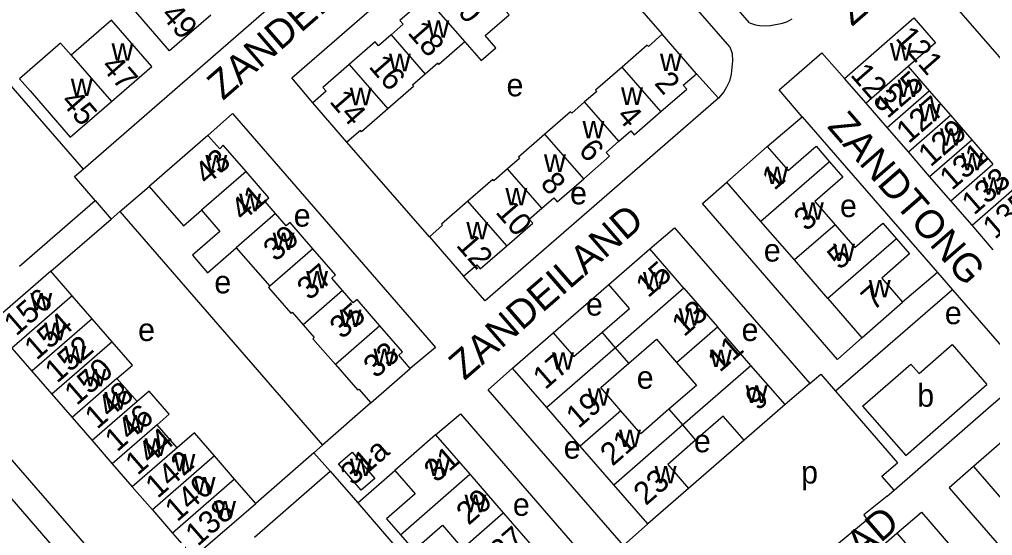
# Model space of a CAD drawing. Extents: x 155854 to 157362, y 383621 to 384685.
# Drawn here: x 156327 to 156498.5, y 384265.7 to 384356.7 of the extents above; entities that cross this region are included whole.
import ezdxf

# ---------------------------------------------------------------- set-up
doc = ezdxf.new("R2010")
doc.units = 0
for name, color, linetype in [('BLT_Basislijn', 7, 'Continuous'), ('BLT_Bebouwing', 7, 'Continuous'), ('BLT_Centroide', 7, 'Continuous'), ('BLT_Huisnummer', 7, 'Continuous'), ('BLT_Huisnummer_ tussenligend', 7, 'Continuous'), ('BLT_Huisnummer_reeks', 7, 'Continuous'), ('BLT_Onderverdeling_panden', 7, 'Continuous'), ('BLT_Straatnaam', 7, 'Continuous')]:
    doc.layers.add(name, color=color, linetype=linetype)

msp = doc.modelspace()

# ---------------------------------------------------------------- linework, layer by layer
at = {"layer": 'BLT_Basislijn'}
for p, q in [((156455.68, 384356.1), (156428.51, 384387.53)), ((156374.97, 384346.36), (156416.08, 384382.07)), ((156452.19, 384351.84), (156425.12, 384382.99)), ((156425.8, 384370.74), (156440.3, 384354.06)), ((156489.82, 384361.43), (156521.66, 384324.72)), ((156317.2, 384354.46), (156338.19, 384330.3)), ((156378.7, 384342), (156374.97, 384346.36)), ((156446.34, 384347.11), (156450.18, 384342.81)), ((156450.18, 384342.81), (156409.08, 384307.1)), ((156360.19, 384336.24), (156364.52, 384340.09)), ((156364.52, 384340.09), (156400.31, 384298.89)), ((156458.81, 384334.27), (156464.96, 384339.52)), ((156464.96, 384339.52), (156488.82, 384312.06)), ((156399.24, 384318.36), (156384.72, 384335.05)), ((156344.7, 384322.81), (156349.83, 384327.25)), ((156447.36, 384324.22), (156451.65, 384328.02)), ((156340.32, 384324.8), (156343.15, 384321.47)), ((156471.21, 384296.77), (156447.36, 384324.22)), ((156332.5, 384312.33), (156343.15, 384321.47)), ((156343.15, 384321.47), (156344.7, 384322.81)), ((156344.7, 384322.81), (156380.43, 384281.68)), ((156438.08, 384316.24), (156442.45, 384319.96)), ((156442.45, 384319.96), (156466.3, 384292.51)), ((156409.08, 384307.1), (156405.27, 384311.42)), ((156488.82, 384312.06), (156482.64, 384306.84)), ((156488.82, 384312.06), (156491.44, 384309.04)), ((156421.07, 384301.47), (156430.86, 384309.97)), ((156491.44, 384309.04), (156470.84, 384291.15)), ((156491.44, 384309.04), (156502.92, 384295.83)), ((156344.96, 384249.98), (156295.38, 384307.06)), ((156475.48, 384300.58), (156471.21, 384296.77)), ((156400.31, 384298.89), (156395.87, 384295.16)), ((156409.61, 384291.43), (156413.91, 384295.21)), ((156466.3, 384292.51), (156468.22, 384294.17)), ((156468.22, 384294.17), (156470.84, 384291.15)), ((156497.78, 384288.23), (156504.47, 384294.05)), ((156466.3, 384292.51), (156461.94, 384288.8)), ((156433.47, 384263.98), (156409.61, 384291.43)), ((156470.84, 384291.15), (156481.75, 384278.57)), ((156388.92, 384289.13), (156380.43, 384281.68)), ((156400.34, 384283.46), (156404.71, 384287.17)), ((156404.71, 384287.17), (156428.56, 384259.71)), ((156481.15, 384273.74), (156497.78, 384288.23)), ((156454.73, 384282.52), (156444.91, 384274.03)), ((156378.87, 384280.31), (156368.63, 384271.4)), ((156380.43, 384281.68), (156378.87, 384280.31)), ((156381.78, 384277.07), (156378.87, 384280.31)), ((156368.42, 384265.44), (156381.78, 384277.07)), ((156381.78, 384277.07), (156386.64, 384271.48)), ((156386.64, 384271.48), (156393.16, 384277.21)), ((156495.16, 384277.93), (156490.89, 384274.12)), ((156479.96, 384272.7), (156481.15, 384273.74)), ((156490.89, 384274.12), (156524.57, 384235.35)), ((156386.64, 384271.48), (156410.41, 384244.02)), ((156481.63, 384266.16), (156485.98, 384269.86)), ((156485.98, 384269.86), (156519.66, 384231.09)), ((156437.74, 384267.78), (156433.47, 384263.98))]:
    msp.add_line(p, q, dxfattribs=at)
for points in [[(156338.19, 384330.3), (156408.21, 384391.13)], [(156455.68, 384356.1), (156456.7, 384355.72), (156457.42, 384355.63), (156458.43, 384355.53), (156459.35, 384355.59), (156461.51, 384356.02), (156462.36, 384356.31), (156463.21, 384356.78)], [(156452.19, 384351.84), (156452.62, 384350.65), (156452.65, 384349.41), (156452.42, 384347.05), (156452.16, 384345.78), (156451.6, 384344.76), (156451.14, 384343.95), (156450.18, 384342.81)], [(156464.96, 384339.52), (156460.88, 384344.27), (156468.44, 384350.79), (156472.41, 384346.29)], [(156270.87, 384342.04), (156329.13, 384275), (156387.17, 384208.19)], [(156340.32, 384324.8), (156336.68, 384328.99), (156338.19, 384330.3)], [(156326.98, 384313.22), (156340.32, 384324.8)], [(156481.15, 384273.74), (156479.02, 384276.18), (156481.75, 384278.57)], [(156479.96, 384272.7), (156475.8, 384269.36), (156476.43, 384268.53), (156471.37, 384264.31), (156463.99, 384258.81), (156457.44, 384254.28), (156446.67, 384247.59)]]:
    msp.add_lwpolyline(points, dxfattribs=at)
at = {"layer": 'BLT_Bebouwing'}
for p, q in [((156343.23, 384356.56), (156336.12, 384350.38)), ((156446.34, 384347.11), (156440.3, 384354.06)), ((156476.21, 384341.92), (156472.41, 384346.29)), ((156384.72, 384335.05), (156378.7, 384342)), ((156479.93, 384337.64), (156476.21, 384341.92)), ((156483.67, 384333.33), (156479.93, 384337.64)), ((156360.19, 384336.24), (156349.83, 384327.25)), ((156451.65, 384328.02), (156458.81, 384334.27)), ((156487.41, 384329.02), (156483.67, 384333.33)), ((156491.16, 384324.72), (156487.41, 384329.02)), ((156457.68, 384321.08), (156451.65, 384328.02)), ((156494.9, 384320.41), (156491.16, 384324.72)), ((156463.58, 384314.29), (156457.68, 384321.08)), ((156498.65, 384316.1), (156494.9, 384320.41)), ((156399.24, 384318.36), (156405.27, 384311.42)), ((156365.19, 384316.44), (156371.1, 384309.65)), ((156444.11, 384309.31), (156438.08, 384316.24)), ((156469.48, 384307.49), (156463.58, 384314.29)), ((156332.5, 384312.33), (156322.37, 384303.51)), ((156339.8, 384303.93), (156336.26, 384308)), ((156444.11, 384309.31), (156450.02, 384302.51)), ((156469.48, 384307.49), (156475.48, 384300.58)), ((156475.48, 384300.58), (156482.64, 384306.84)), ((156343.34, 384299.86), (156339.8, 384303.93)), ((156421.1, 384301.42), (156421.11, 384301.42)), ((156455.92, 384295.72), (156450.02, 384302.51)), ((156461.94, 384288.8), (156455.92, 384295.72)), ((156388.92, 384289.13), (156395.87, 384295.16)), ((156419.92, 384288.29), (156413.91, 384295.21)), ((156347.71, 384289.34), (156344.16, 384293.42)), ((156425.83, 384281.49), (156419.92, 384288.29)), ((156354.79, 384281.19), (156351.25, 384285.26)), ((156502.37, 384284.18), (156495.16, 384277.93)), ((156400.34, 384283.46), (156393.16, 384277.21)), ((156400.34, 384283.46), (156406.37, 384276.53)), ((156431.73, 384274.7), (156425.83, 384281.49)), ((156364.92, 384275.68), (156361.39, 384279.77)), ((156495.16, 384277.93), (156500.88, 384271.35)), ((156368.63, 384271.4), (156364.92, 384275.68)), ((156406.37, 384276.53), (156412.27, 384269.73)), ((156437.74, 384267.78), (156431.73, 384274.7)), ((156412.27, 384269.73), (156418.18, 384262.93)), ((156474.43, 384259.91), (156481.63, 384266.16)), ((156481.63, 384266.16), (156487.34, 384259.59))]:
    msp.add_line(p, q, dxfattribs=at)
for points in [[(156360.7, 384357.43), (156353.45, 384351.15), (156346.37, 384359.3)], [(156398.69, 384360.55), (156394.03, 384356.5), (156394.62, 384355.83), (156392.48, 384353.98)], [(156405.5, 384352.71), (156408.35, 384349.42), (156410.96, 384351.68), (156409.09, 384353.84), (156413.28, 384357.48), (156412.1, 384358.83)], [(156343.2, 384342.23), (156350.31, 384348.4), (156343.23, 384356.56)], [(156472.41, 384346.29), (156484.66, 384356.95)], [(156484.66, 384356.95), (156488.45, 384352.58), (156483.62, 384348.38)], [(156440.3, 384354.06), (156437.85, 384351.92), (156437.65, 384352.15), (156433.21, 384348.28)], [(156336.12, 384350.38), (156334.21, 384352.5), (156327, 384346.24), (156328.87, 384344.09), (156335.95, 384335.94), (156343.2, 384342.23)], [(156392.48, 384353.98), (156390.27, 384352.05), (156389.68, 384352.72), (156385.11, 384348.75)], [(156405.5, 384352.71), (156400.92, 384348.72), (156400.72, 384348.95), (156398.51, 384347.03)], [(156385.11, 384348.75), (156380.44, 384344.7), (156381.03, 384344.03), (156378.7, 384342)], [(156433.21, 384348.28), (156428.54, 384344.23), (156428.74, 384344), (156426.61, 384342.15)], [(156483.62, 384348.38), (156487.35, 384344.09)], [(156398.51, 384347.03), (156396.27, 384345.09), (156396.47, 384344.86), (156391.92, 384340.91)], [(156440.03, 384340.43), (156444.6, 384344.4), (156443.99, 384345.07), (156446.34, 384347.11)], [(156487.35, 384344.09), (156491.09, 384339.78)], [(156426.61, 384342.15), (156424.33, 384340.17), (156424.13, 384340.39), (156419.62, 384336.48)], [(156391.92, 384340.91), (156387.3, 384336.9), (156387.11, 384337.12), (156384.72, 384335.05)], [(156432.64, 384335.21), (156434.77, 384337.05), (156435.36, 384336.37), (156440.03, 384340.43)], [(156491.09, 384339.78), (156494.84, 384335.47)], [(156366.92, 384329.87), (156362.9, 384334.51), (156362.31, 384333.89), (156360.19, 384336.24)], [(156419.62, 384336.48), (156414.93, 384332.4), (156415.13, 384332.18), (156413.03, 384330.35)], [(156426.45, 384328.62), (156431, 384332.59), (156430.41, 384333.26), (156432.64, 384335.21)], [(156494.84, 384335.47), (156498.58, 384331.17)], [(156458.81, 384334.27), (156462.48, 384330.04), (156467.41, 384334.33), (156469.79, 384331.59)], [(156413.03, 384330.35), (156410.62, 384328.26), (156410.43, 384328.49), (156406.04, 384324.67)], [(156469.79, 384331.59), (156472.13, 384328.89), (156467.2, 384324.61), (156470.75, 384320.51)], [(156372.14, 384322.48), (156370.24, 384324.67), (156370.92, 384325.26), (156366.92, 384329.87)], [(156419.06, 384323.4), (156421.17, 384325.24), (156421.77, 384324.55), (156426.45, 384328.62)], [(156349.83, 384327.25), (156355.88, 384320.29), (156359.07, 384323.05)], [(156406.04, 384324.67), (156401.38, 384320.62), (156401.58, 384320.4), (156399.24, 384318.36)], [(156412.88, 384316.8), (156417.45, 384320.76), (156416.82, 384321.46), (156419.06, 384323.4)], [(156359.07, 384323.05), (156362.3, 384319.32), (156357.46, 384315.12), (156360.14, 384312.04), (156365.2, 384316.44)], [(156378.72, 384316.28), (156374.69, 384320.91), (156374.02, 384320.32), (156372.14, 384322.48)], [(156470.75, 384320.51), (156474.25, 384316.5), (156479.18, 384320.78), (156481.59, 384318.01)], [(156405.27, 384311.42), (156407.6, 384313.44), (156408.2, 384312.75), (156412.88, 384316.8)], [(156481.59, 384318.01), (156483.9, 384315.35), (156478.97, 384311.06), (156482.64, 384306.84)], [(156383.94, 384308.89), (156382.03, 384311.09), (156382.72, 384311.68), (156378.72, 384316.28)], [(156430.86, 384309.97), (156438.08, 384316.24)], [(156336.26, 384308), (156332.5, 384312.33)], [(156371.1, 384309.65), (156370.87, 384309.45), (156374.81, 384304.92), (156375.03, 384305.12), (156377, 384302.86)], [(156429.68, 384301.55), (156434.52, 384305.76), (156430.86, 384309.97)], [(156390.53, 384302.69), (156386.5, 384307.33), (156385.82, 384306.73), (156383.94, 384308.89)], [(156377, 384302.86), (156378.94, 384300.62), (156378.72, 384300.42), (156382.67, 384295.87)], [(156395.87, 384295.16), (156393.84, 384297.5), (156394.53, 384298.09), (156390.53, 384302.69)], [(156413.91, 384295.21), (156421.07, 384301.47)], [(156421.07, 384301.47), (156424.73, 384297.26), (156429.68, 384301.55)], [(156344.16, 384293.42), (156346.89, 384295.78), (156343.34, 384299.86)], [(156434.4, 384296.12), (156439.25, 384300.33), (156442.8, 384296.24)], [(156475.61, 384288.51), (156484.13, 384295.93), (156485.55, 384294.3), (156491.39, 384299.39), (156497.52, 384292.33)], [(156325.63, 384298.77), (156329.17, 384294.7)], [(156382.67, 384295.87), (156386.61, 384291.34), (156386.83, 384291.53), (156388.92, 384289.13)], [(156433.01, 384287.73), (156429.45, 384291.82), (156434.4, 384296.12)], [(156442.8, 384296.24), (156446.32, 384292.19), (156441.47, 384287.98)], [(156329.17, 384294.7), (156332.71, 384290.62)], [(156495.65, 384290.69), (156497.52, 384292.33)], [(156332.71, 384290.62), (156336.25, 384286.54)], [(156351.25, 384285.26), (156353.38, 384287.12), (156349.83, 384291.2), (156347.71, 384289.34)], [(156483.2, 384279.84), (156495.65, 384290.69)], [(156441.47, 384287.98), (156436.52, 384283.68), (156433.01, 384287.73)], [(156461.94, 384288.8), (156454.73, 384282.52)], [(156475.61, 384288.51), (156483.2, 384279.84)], [(156336.25, 384286.54), (156339.79, 384282.47)], [(156454.73, 384282.52), (156451.05, 384286.76), (156446.17, 384282.52)], [(156361.39, 384279.77), (156357.85, 384283.85), (156354.79, 384281.19)], [(156339.79, 384282.47), (156343.34, 384278.39)], [(156446.17, 384282.52), (156441.25, 384278.25), (156444.91, 384274.03)], [(156385.25, 384280.08), (156385.65, 384280.43)], [(156385.65, 384280.43), (156389.61, 384275.8)], [(156383.25, 384278.39), (156385.25, 384280.08)], [(156343.34, 384278.39), (156346.88, 384274.31)], [(156387.2, 384273.75), (156383.25, 384278.39)], [(156393.16, 384277.21), (156396.74, 384273.09), (156391.68, 384268.7), (156394.14, 384265.87)], [(156389.61, 384275.8), (156387.2, 384273.75)], [(156346.88, 384274.31), (156350.42, 384270.24)], [(156444.91, 384274.03), (156437.74, 384267.78)], [(156350.42, 384270.24), (156353.96, 384266.16)], [(156353.96, 384266.16), (156357.66, 384261.91), (156368.63, 384271.4)], [(156394.14, 384265.87), (156396.49, 384263.17), (156401.55, 384267.55), (156405.09, 384263.47)]]:
    msp.add_lwpolyline(points, dxfattribs=at)
at = {"layer": 'BLT_Onderverdeling_panden'}
for p, q in [((156398.69, 384360.55), (156405.5, 384352.71)), ((156392.48, 384353.98), (156398.51, 384347.03)), ((156336.12, 384350.38), (156343.2, 384342.23)), ((156385.11, 384348.75), (156391.92, 384340.91)), ((156440.03, 384340.43), (156433.21, 384348.28)), ((156483.62, 384348.38), (156476.21, 384341.92)), ((156479.93, 384337.64), (156487.35, 384344.09)), ((156432.64, 384335.21), (156426.61, 384342.15)), ((156483.67, 384333.33), (156491.09, 384339.78)), ((156426.45, 384328.62), (156419.62, 384336.48)), ((156487.41, 384329.02), (156494.84, 384335.47)), ((156419.06, 384323.4), (156413.03, 384330.35)), ((156469.79, 384331.59), (156457.68, 384321.08)), ((156491.16, 384324.72), (156498.58, 384331.17)), ((156366.92, 384329.87), (156359.07, 384323.05)), ((156494.9, 384320.41), (156502.33, 384326.86)), ((156412.88, 384316.8), (156406.04, 384324.67)), ((156372.14, 384322.48), (156365.19, 384316.44)), ((156470.75, 384320.51), (156463.58, 384314.29)), ((156481.59, 384318.01), (156469.48, 384307.49)), ((156378.72, 384316.28), (156371.1, 384309.65)), ((156336.26, 384308), (156325.63, 384298.77)), ((156383.94, 384308.89), (156377, 384302.86)), ((156444.11, 384309.31), (156432.05, 384298.83)), ((156339.8, 384303.93), (156329.17, 384294.7)), ((156390.53, 384302.69), (156382.67, 384295.87)), ((156432.05, 384298.83), (156429.68, 384301.55)), ((156442.8, 384296.24), (156450.02, 384302.51)), ((156343.34, 384299.86), (156332.71, 384290.62)), ((156432.05, 384298.83), (156419.92, 384288.29)), ((156434.4, 384296.12), (156432.05, 384298.83)), ((156443.86, 384285.24), (156455.92, 384295.72)), ((156344.16, 384293.42), (156336.25, 384286.54)), ((156347.71, 384289.34), (156339.79, 384282.47)), ((156433.01, 384287.73), (156425.83, 384281.49)), ((156441.47, 384287.98), (156443.86, 384285.24)), ((156351.25, 384285.26), (156343.34, 384278.39)), ((156431.73, 384274.7), (156443.86, 384285.24)), ((156443.86, 384285.24), (156446.17, 384282.52)), ((156354.79, 384281.19), (156346.88, 384274.31)), ((156361.39, 384279.77), (156350.42, 384270.24)), ((156364.92, 384275.68), (156353.96, 384266.16)), ((156394.14, 384265.87), (156406.37, 384276.53)), ((156405.09, 384263.47), (156412.27, 384269.73))]:
    msp.add_line(p, q, dxfattribs=at)

# ---------------------------------------------------------------- texts
at = {"layer": 'BLT_Centroide'}
for s, p in [('w', (156398.89, 384353.45)), ('w', (156343.22, 384349.39)), ('w', (156480.42, 384349.44)), ('w', (156392.11, 384347.56)), ('w', (156439.88, 384347.59)), ('w', (156336.03, 384343.16)), ('e', (156412.84, 384343.13)), ('w', (156481.78, 384343)), ('w', (156385.21, 384341.56)), ('w', (156433.03, 384341.62)), ('w', (156485.51, 384338.72)), ('w', (156426.23, 384335.72)), ('w', (156489.26, 384334.41)), ('w', (156359.75, 384329.73)), ('w', (156419.44, 384329.81)), ('w', (156492.99, 384330.09)), ('w', (156458.62, 384327.69)), ('w', (156496.74, 384325.78)), ('w', (156412.64, 384323.92)), ('e', (156424.04, 384324.09)), ('w', (156365.72, 384322.88)), ('e', (156471.62, 384321.85)), ('e', (156375.33, 384320.17)), ('w', (156464.91, 384321.39)), ('w', (156405.75, 384317.94)), ('w', (156371.62, 384316.06)), ('e', (156458.19, 384314.01)), ('w', (156470.41, 384314.12)), ('e', (156361.34, 384308.41)), ('w', (156377.52, 384309.28)), ('w', (156436.89, 384309.12)), ('w', (156476.69, 384307.69)), ('w', (156328.9, 384305.41)), ('e', (156426.84, 384304.49)), ('e', (156490.1, 384302.98)), ('w', (156383.42, 384302.47)), ('w', (156443.18, 384302.72)), ('w', (156331.35, 384300.16)), ('e', (156347.9, 384300.01)), ('e', (156454.27, 384300.01)), ('w', (156334.9, 384296.09)), ('w', (156389.38, 384295.62)), ('w', (156420.86, 384294.94)), ('w', (156448.7, 384295.41)), ('w', (156338.43, 384292.03)), ('e', (156435.79, 384291.61)), ('b', (156485.24, 384288.44)), ('w', (156341.98, 384287.94)), ('w', (156427.16, 384288.62)), ('w', (156454.99, 384289.12)), ('w', (156345.52, 384283.88)), ('w', (156432.67, 384281.34)), ('w', (156349.05, 384279.78)), ('e', (156422.92, 384279.29)), ('e', (156445.87, 384280.41)), ('w', (156354.13, 384277.03)), ('w', (156385.23, 384276.22)), ('w', (156399.03, 384276.22)), ('w', (156438.95, 384274.91)), ('p', (156464.77, 384274.9)), ('w', (156357.68, 384272.97)), ('w', (156361.3, 384268.78)), ('w', (156405.44, 384269.84)), ('e', (156413.96, 384269.21))]:
    msp.add_text(s, height=4, dxfattribs=at).set_placement(p)
at = {"layer": 'BLT_Huisnummer'}
for s, rotation, p in [('49', 310.9828, (156351.77, 384357.36)), ('18', 310.985, (156395.26, 384354.28)), ('47', 310.9828, (156341.22, 384348.29)), ('2', 310.985, (156438.76, 384345.37)), ('14', 310.985, (156381.48, 384342.16)), ('45', 310.9828, (156334.11, 384342.13)), ('127', 40.9795, (156483.7, 384334.66)), ('6', 310.985, (156425.36, 384333.51)), ('43', 40.9803, (156360.02, 384327.34)), ('131', 40.9795, (156491.34, 384326.43)), ('1', 40.9747, (156460.04, 384326.43)), ('135', 40.9795, (156498.94, 384317.8)), ('12', 310.985, (156403.82, 384316.83)), ('5', 40.9747, (156471.56, 384312.41)), ('37', 40.9803, (156378.09, 384307.03)), ('15', 40.9747, (156437.78, 384307.49)), ('7', 40.9747, (156477.51, 384305.22)), ('156', 40.9826, (156326.4, 384300.76)), ('33', 40.9803, (156389.79, 384293.3)), ('17', 40.9915, (156419.66, 384291.31)), ('150', 40.9826, (156337.07, 384288.52)), ('19', 40.9915, (156425.5, 384284.46)), ('9', 40.9747, (156457.13, 384287.59)), ('146', 40.9826, (156344.2, 384280.34)), ('21', 40.9915, (156431.52, 384277.83)), ('142', 40.9826, (156351.34, 384272.16)), ('31a', 41.029, (156385.77, 384274.38)), ('31', 40.9839, (156400.47, 384274.91)), ('23', 40.993, (156437.39, 384270.89)), ('138', 40.9826, (156358.4, 384263.71))]:
    msp.add_text(s, height=4, rotation=rotation, dxfattribs=at).set_placement(p)
at = {"layer": 'BLT_Huisnummer_ tussenligend'}
for s, rotation, p in [('20', 310.985, (156402.12, 384360.18)), ('16', 310.985, (156388.4, 384348.32)), ('125', 40.9795, (156479.97, 384339.07)), ('4', 310.985, (156432.09, 384339.54)), ('129', 40.9795, (156487.58, 384330.56)), ('133', 40.9795, (156495.24, 384322.06)), ('8', 310.985, (156418.63, 384327.67)), ('41', 40.9803, (156366.38, 384320.97)), ('10', 310.985, (156410.75, 384322.67)), ('3', 40.9747, (156465.66, 384319.21)), ('39', 40.9803, (156372.13, 384313.86)), ('35', 40.9803, (156383.84, 384300.2)), ('13', 40.9747, (156444.13, 384300.63)), ('154', 40.9826, (156330, 384296.5)), ('152', 40.9826, (156333.61, 384292.46)), ('11', 40.9747, (156450.43, 384294.38)), ('148', 40.9826, (156340.67, 384284.33)), ('144', 40.9826, (156347.79, 384276.21)), ('140', 40.9826, (156354.79, 384268.03)), ('29', 40.9839, (156406.15, 384267.43)), ('27', 40.9839, (156412.04, 384260.75))]:
    msp.add_text(s, height=4, rotation=rotation, dxfattribs=at).set_placement(p)
at = {"layer": 'BLT_Huisnummer_reeks'}
for s, rotation, p in [('121', 310.9948, (156481.27, 384353.31)), ('123', 310.9877, (156473.31, 384346.84))]:
    msp.add_text(s, height=4, rotation=rotation, dxfattribs=at).set_placement(p)
at = {"layer": 'BLT_Straatnaam'}
for s, rotation, p in [('ZANDTONG', 40.9818, (156473.73, 384355.33)), ('ZANDEILAND', 40.9825, (156362.85, 384342.29)), ('ZANDTONG', 310.9823, (156469.23, 384337.74)), ('ZANDEILAND', 40.9825, (156405.43, 384292.96)), ('ZANDPAD', 40.982, (156458.32, 384246.58))]:
    msp.add_text(s, height=5, rotation=rotation, dxfattribs=at).set_placement(p)

doc.saveas('drawing.dxf')
